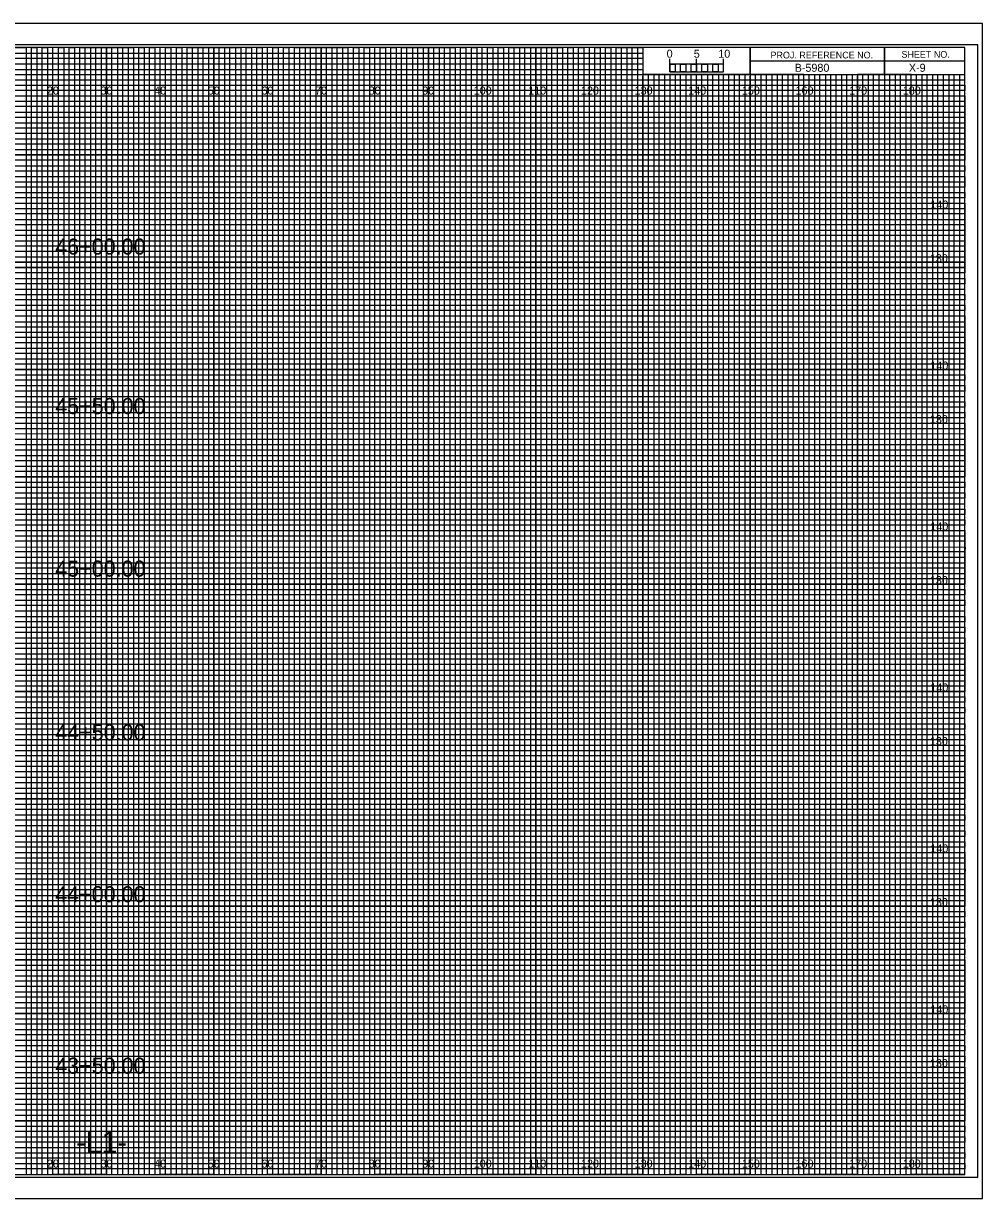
# Model space of a CAD drawing. Extents: x -13 to 323, y -5 to 3294.
# Drawn here: x 144.5 to 323.3, y 1755.5 to 1974.5 of the extents above; entities that cross this region are included whole.
import ezdxf

# ---------------------------------------------------------------- set-up
doc = ezdxf.new("R2010")
doc.units = 0
for name, color, linetype in [('Prop XS Alignment Label', 7, 'Continuous'), ('Prop XS Bar Scale Labels', 7, 'Continuous'), ('Prop XS Elevation Labels', 7, 'Continuous'), ('Prop XS Offset Labels', 7, 'Continuous'), ('Prop XS Project Number', 7, 'Continuous'), ('Prop XS Sheet Number', 7, 'Continuous'), ('Prop XS Station Labels', 7, 'Continuous'), ('Scratch_Level_0', 7, 'Continuous'), ('Sheet Cross Section CELL', 7, 'Continuous'), ('Sheet Cross Section Grid Major CELL', 7, 'Continuous'), ('Sheet Cross Section Grid Middle CELL', 7, 'Continuous'), ('Sheet Cross Section Grid Minor 1 CELL', 7, 'Continuous'), ('Sheet Cross Section Grid Minor 2 CELL', 7, 'Continuous'), ('Sheet Cross Section Scale CELL', 7, 'Continuous'), ('Sheet Cutting Line CELL', 7, 'Continuous'), ('Sheet DOT Grid CELL', 7, 'Continuous'), ('Sheet Plot Border Inside CELL', 7, 'Continuous'), ('Sheet Plot Border Outside CELL', 7, 'Continuous')]:
    doc.layers.add(name, color=color, linetype=linetype)

msp = doc.modelspace()

# ---------------------------------------------------------------- linework, layer by layer
at = {"layer": 'Scratch_Level_0'}
msp.add_lwpolyline([(310, 1800), (10, 1800), (10, 1770), (310, 1770)], close=True, dxfattribs=at)
at = {"layer": 'Sheet Cross Section CELL'}
for p, q in [((305, 1970), (305, 1965)), ((305, 1965), (305, 1970)), ((280, 1967.5), (280, 1965)), ((320, 1967.49), (280, 1967.49)), ((280, 1965), (320, 1965))]:
    msp.add_line(p, q, dxfattribs=at)
for points in [[(320, 1970), (0, 1970), (0, 1760), (320, 1760)], [(280, 1970), (260, 1970), (260, 1965.03), (280, 1965.03)], [(320, 1970), (280, 1970), (280, 1965), (320, 1965)]]:
    msp.add_lwpolyline(points, close=True, dxfattribs=at)
at = {"layer": 'Sheet Cross Section Grid Major CELL'}
for p, q in [((150, 1970), (140, 1970)), ((150, 1760), (150, 1970)), ((170, 1970), (160, 1970)), ((160, 1970), (160, 1760)), ((170, 1760), (170, 1970)), ((190, 1970), (180, 1970)), ((180, 1970), (180, 1760)), ((190, 1760), (190, 1970)), ((210, 1970), (200, 1970)), ((200, 1970), (200, 1760)), ((210, 1760), (210, 1970)), ((230, 1970), (220, 1970)), ((220, 1970), (220, 1760)), ((230, 1760), (230, 1970)), ((250, 1970), (240, 1970)), ((240, 1970), (240, 1760)), ((250, 1760), (250, 1970)), ((260, 1970), (260, 1760)), ((270, 1760), (270, 1965)), ((290, 1965), (280, 1965)), ((280, 1965), (280, 1760)), ((290, 1760), (290, 1965)), ((310, 1965), (300, 1965)), ((300, 1965), (300, 1760)), ((310, 1760), (310, 1965)), ((160, 1760), (150, 1760)), ((180, 1760), (170, 1760)), ((200, 1760), (190, 1760)), ((220, 1760), (210, 1760)), ((240, 1760), (230, 1760)), ((260, 1760), (250, 1760)), ((280, 1760), (270, 1760)), ((300, 1760), (290, 1760)), ((320, 1760), (310, 1760)), ((320, 1760), (320, 1760))]:
    msp.add_line(p, q, dxfattribs=at)
for points in [[(0, 1960), (320, 1960), (320, 1950), (0, 1950)], [(0, 1940), (320, 1940), (320, 1930), (0, 1930)], [(0, 1920), (320, 1920), (320, 1910), (0, 1910)], [(0, 1900), (320, 1900), (320, 1890), (0, 1890)], [(0, 1880), (320, 1880), (320, 1870), (0, 1870)], [(0, 1860), (320, 1860), (320, 1850), (0, 1850)], [(0, 1840), (320, 1840), (320, 1830), (0, 1830)], [(0, 1820), (320, 1820), (320, 1810), (0, 1810)], [(0, 1800), (320, 1800), (320, 1790), (0, 1790)], [(0, 1780), (320, 1780), (320, 1770), (0, 1770)]]:
    msp.add_lwpolyline(points, dxfattribs=at)
at = {"layer": 'Sheet Cross Section Grid Middle CELL'}
for points in [[(135, 1970), (145, 1970), (145, 1760), (155, 1760), (155, 1970), (165, 1970), (165, 1760), (175, 1760), (175, 1970), (185, 1970), (185, 1760), (195, 1760), (195, 1970), (205, 1970), (205, 1760), (215, 1760), (215, 1970), (225, 1970), (225, 1760), (235, 1760), (235, 1970), (245, 1970), (245, 1760), (255, 1760), (255, 1970), (259.93, 1970), (260, 1970), (260, 1965), (264.99, 1965), (264.99, 1760), (275, 1760), (275, 1965), (285, 1965), (285, 1760), (295, 1760), (295, 1965), (305, 1965), (305, 1760), (315, 1760), (315, 1965)], [(0, 1965), (275, 1965)], [(0, 1945), (320, 1945), (320, 1955), (0, 1955)], [(0, 1925), (320, 1925), (320, 1935), (0, 1935)], [(0, 1905), (320, 1905), (320, 1915), (0, 1915)], [(0, 1885), (320, 1885), (320, 1895), (0, 1895)], [(0, 1865), (320, 1865), (320, 1875), (0, 1875)], [(0, 1845), (320, 1845), (320, 1855), (0, 1855)], [(0, 1825), (320, 1825), (320, 1835), (0, 1835)], [(0, 1805), (320, 1805), (320, 1815), (0, 1815)], [(0, 1785), (320, 1785), (320, 1795), (0, 1795)], [(0, 1765), (320, 1765), (320, 1775), (0, 1775)]]:
    msp.add_lwpolyline(points, dxfattribs=at)
at = {"layer": 'Sheet Cross Section Grid Minor 1 CELL'}
for p, q in [((0, 1969), (260, 1969)), ((260, 1969), (260, 1967.98)), ((260, 1967.98), (0, 1967.98)), ((0, 1967), (260, 1967)), ((260, 1967), (260, 1965.89)), ((260, 1965.89), (0, 1965.89)), ((0, 1964), (320, 1964))]:
    msp.add_line(p, q, dxfattribs=at)
for points in [[(0, 1963), (270, 1963), (320, 1963), (320, 1962), (0, 1962)], [(0, 1961), (320, 1961), (320, 1959), (0, 1959)], [(0, 1958), (320, 1958), (320, 1957), (0, 1956.98)], [(0, 1956), (320, 1956), (320, 1954), (0, 1954)], [(0, 1953), (320, 1953), (320, 1952), (0, 1952)], [(0, 1951), (320, 1951), (320, 1949), (0, 1949)], [(0, 1948), (320, 1948), (320, 1947), (0, 1947)], [(0, 1946), (320, 1946), (320, 1944), (0, 1944)], [(0, 1943), (320, 1943), (320, 1942), (0, 1942)], [(0, 1941), (320, 1941), (320, 1939), (0, 1939)], [(0, 1938), (320, 1938), (320, 1937), (0, 1937)], [(0, 1936), (320, 1936), (320, 1933.95), (320, 1933), (320, 1932), (0, 1932)], [(0, 1934), (320, 1934), (320, 1933), (0, 1933)], [(0, 1931), (320, 1931), (320, 1929), (0, 1929.03)], [(0, 1929.03), (320, 1929), (320, 1928), (0, 1928)], [(0, 1927), (320, 1927), (320, 1926), (0, 1926)], [(0, 1924), (320, 1924), (320, 1923), (0, 1923)], [(0, 1922), (320, 1922), (320, 1921), (0, 1921)], [(-0.07, 1918.89), (320, 1918.89), (320, 1917.88), (-0.07, 1917.88)], [(0, 1917), (320, 1917), (320, 1916), (0, 1916)], [(0, 1914), (320, 1914), (320, 1913), (0, 1913)], [(0, 1912), (320, 1912), (320, 1911), (0, 1911)], [(0, 1909), (320, 1909), (320, 1908), (0, 1908)], [(0, 1907), (320, 1907), (320, 1906), (0, 1906)], [(0, 1904), (320, 1904), (320, 1903), (0, 1903)], [(0, 1902), (320, 1902), (320, 1901), (0, 1901)], [(0, 1899), (320, 1899), (319.99, 1897.98), (0, 1898)], [(0, 1897), (320, 1897), (320, 1896), (0, 1896)], [(0, 1894), (320, 1894), (320, 1893), (0, 1893)], [(0, 1892), (320, 1892), (320, 1891), (0, 1891)], [(0, 1889), (320, 1889), (320, 1888), (0, 1888)], [(0, 1887), (320, 1887), (320, 1886), (0, 1886)], [(0, 1884), (320, 1884), (320, 1883), (0, 1883)], [(0, 1882), (320, 1882), (320, 1881), (0, 1881)], [(0, 1879), (320, 1879), (320, 1878), (0, 1878)], [(0, 1876.99), (320.07, 1876.91), (320, 1876), (0, 1876)], [(0, 1874), (320, 1874), (320, 1873), (0, 1873)], [(0, 1872), (320, 1872), (320, 1871), (0, 1871)], [(0, 1869), (320, 1869), (320, 1868), (0, 1868)], [(0, 1867), (320, 1867), (320, 1866), (0, 1866)], [(0, 1864), (320, 1864), (320, 1863), (0, 1863)], [(0, 1862), (320, 1862), (320, 1861), (0, 1861)], [(0, 1859), (320, 1859), (320, 1858), (0, 1858)], [(0, 1857), (320, 1857), (320, 1856), (0, 1856)], [(0, 1854), (320, 1854), (320, 1853), (0, 1853)], [(0, 1852), (320, 1852), (320, 1851), (0, 1851)], [(0, 1849), (320, 1849), (320, 1848), (0, 1848)], [(0, 1847), (320, 1847), (320, 1846), (0, 1846)], [(0, 1844), (320, 1844), (320, 1843), (0, 1843)], [(0, 1842), (320, 1842), (320, 1841), (0, 1841)], [(0, 1839), (320, 1839), (319.99, 1837.98), (0, 1838)], [(0, 1837), (320, 1837), (320, 1836), (0, 1836)], [(0, 1834), (320, 1834), (320, 1833), (0, 1833)], [(0, 1832), (320, 1832), (320, 1831), (0, 1831)], [(0, 1829), (320, 1829), (320, 1828), (0, 1828)], [(0, 1827), (320, 1827), (320, 1826), (0, 1826)], [(0, 1824), (320, 1824), (320, 1823), (0, 1823)], [(0, 1822), (320, 1822), (320, 1821), (0, 1821)], [(0, 1819), (320, 1819), (320, 1818), (0, 1818)], [(0, 1816.99), (320.07, 1816.91), (320, 1816), (0, 1816)], [(0, 1814), (320, 1814), (320, 1813), (0, 1813)], [(0, 1812), (320, 1812), (320, 1811), (0, 1811)], [(0, 1809), (320, 1809), (320, 1808), (0, 1808)], [(0, 1807), (320, 1807), (320, 1806), (0, 1806)], [(0, 1804), (320, 1804), (320, 1803), (0, 1803)], [(0, 1802), (320, 1802), (320, 1801), (0, 1801)], [(0, 1799), (320, 1799), (320, 1798), (0, 1798)], [(0, 1797), (320, 1797), (320, 1796), (0, 1796)], [(0, 1794), (320, 1794), (320, 1793), (0, 1793)], [(0, 1792), (320, 1792), (320, 1791), (0, 1791)], [(0, 1789), (320, 1789), (320, 1788), (0, 1788)], [(0, 1787), (320, 1787), (320, 1786), (0, 1786)], [(0, 1784), (320, 1784), (320, 1783), (0, 1783)], [(0, 1782), (320, 1782), (320, 1781), (0, 1781)], [(0, 1779), (320, 1779), (320, 1778), (0, 1778)], [(0, 1777), (320, 1777), (320, 1776), (0, 1776)], [(0, 1774), (320, 1774), (320, 1773), (0, 1773)], [(0, 1772), (320, 1772), (320, 1771), (0, 1771)], [(0, 1769), (320, 1769), (320, 1768), (0, 1768)], [(0, 1767), (320, 1767), (320, 1766), (0, 1766)], [(0, 1764), (320, 1764), (320, 1763), (0, 1763)], [(0, 1762), (320, 1762), (320, 1761), (0, 1761)]]:
    msp.add_lwpolyline(points, dxfattribs=at)
at = {"layer": 'Sheet Cross Section Grid Minor 2 CELL'}
for p, q in [((267, 1965), (266.01, 1965)), ((266.01, 1965), (266.01, 1760)), ((267, 1760), (267, 1965)), ((269, 1965), (268, 1965)), ((268, 1965), (268, 1760)), ((269, 1760), (269, 1965)), ((266.01, 1760), (265, 1760)), ((268, 1760), (267, 1760))]:
    msp.add_line(p, q, dxfattribs=at)
for points in [[(145, 1760), (146, 1760), (146, 1970), (147, 1970), (147, 1760)], [(147, 1760), (148, 1760), (148, 1970), (149, 1970), (149, 1760)], [(150, 1760), (151, 1760), (151, 1970), (152, 1970), (152, 1760)], [(152, 1760), (153, 1760), (153, 1970), (154, 1970), (154, 1760)], [(155, 1760), (156, 1760), (156, 1970), (157, 1970), (157, 1760)], [(157, 1760), (158, 1760), (158, 1970), (159, 1970), (159, 1760)], [(160, 1760), (161, 1760), (161, 1970), (162, 1970), (162, 1760)], [(162, 1760), (163, 1760), (163, 1970), (164, 1970), (164, 1760)], [(165, 1760), (166, 1760), (166, 1970), (167, 1970), (167, 1760)], [(167, 1760), (168, 1760), (168, 1970), (169, 1970), (169, 1760)], [(170, 1760), (171, 1760), (171, 1970), (172, 1970), (172, 1760)], [(172, 1760), (173, 1760), (173, 1970), (174, 1970), (174, 1760)], [(175, 1760), (176, 1760), (176, 1970), (177, 1970), (177, 1760)], [(177, 1760), (178, 1760), (178, 1970), (179, 1970), (179, 1760)], [(180, 1760), (181, 1760), (181, 1970), (182, 1970), (182, 1760)], [(182, 1760), (183, 1760), (183, 1970), (184, 1970), (184, 1760)], [(185, 1760), (186, 1760), (186, 1970), (187, 1970), (187, 1760)], [(187, 1760), (188, 1760), (188, 1970), (189, 1970), (189, 1760)], [(190, 1760), (191, 1760), (191, 1970), (192, 1970), (192, 1760)], [(192, 1760), (193, 1760), (193, 1970), (194, 1970), (194, 1760)], [(195, 1760), (196, 1760), (196, 1970), (197, 1970), (197, 1760)], [(197, 1760), (198, 1760), (198, 1970), (199, 1970), (199, 1760)], [(200, 1760), (201, 1760), (201, 1970), (202, 1970), (202, 1760)], [(202, 1760), (203, 1760), (203, 1970), (204, 1970), (204, 1760)], [(205, 1760), (206, 1760), (206, 1970), (207, 1970), (207, 1760)], [(207, 1760), (208, 1760), (208, 1970), (209, 1970), (209, 1760)], [(210, 1760), (211, 1760), (211, 1970), (212, 1970), (212, 1760)], [(212, 1760), (213, 1760), (213, 1970), (214, 1970), (214, 1760)], [(215, 1760), (216, 1760), (216, 1970), (217, 1970), (217, 1760)], [(217, 1760), (218, 1760), (218, 1970), (219, 1970), (219, 1760)], [(220, 1760), (221, 1760), (221, 1970), (222, 1970), (222, 1760)], [(222, 1760), (223, 1760), (223, 1970), (224, 1970), (224, 1760)], [(225, 1760), (226, 1760), (226, 1970), (227, 1970), (227, 1760)], [(227, 1760), (228, 1760), (228, 1970), (229, 1970), (229, 1760)], [(230, 1760), (231, 1760), (231, 1970), (232, 1970), (232, 1760)], [(232, 1760), (233, 1760), (233, 1970), (234, 1970), (234, 1760)], [(235, 1760), (236, 1760), (236, 1970), (237, 1970), (237, 1760)], [(237, 1760), (238, 1760), (238, 1970), (239, 1970), (239, 1760)], [(240, 1760), (241, 1760), (241, 1970), (242, 1970), (242, 1760)], [(242, 1760), (243, 1760), (243, 1970), (244, 1970), (244, 1760)], [(245, 1760), (246, 1760), (246, 1970), (247, 1970), (247, 1760)], [(247, 1760), (248, 1760), (248, 1970), (249, 1970), (249, 1760)], [(250, 1760), (251, 1760), (251, 1970), (252, 1970), (252, 1760)], [(252, 1760), (253, 1760), (253, 1970), (254, 1970), (254, 1760)], [(255, 1760), (256, 1760), (256, 1970), (257, 1970), (257, 1760)], [(257, 1760), (258, 1760), (258, 1970), (259, 1970), (259, 1760)], [(260, 1760), (261, 1760), (261, 1965), (262.02, 1965), (262.02, 1760)], [(262, 1760), (263, 1760), (263, 1965), (263.99, 1965), (263.99, 1760)], [(270, 1760), (270.98, 1760), (270.98, 1965), (272, 1965), (272, 1760)], [(272, 1760), (273, 1760), (273, 1965), (274.05, 1965), (274.05, 1760)], [(275, 1760), (276, 1760), (276, 1965), (277, 1965), (277, 1760)], [(277, 1760), (278, 1760), (278, 1965), (279, 1965), (279, 1760)], [(280, 1760), (281, 1760), (281, 1965), (282, 1965), (282, 1760)], [(282, 1760), (283, 1760), (283, 1965), (284, 1965), (284, 1760)], [(285, 1760), (286, 1760), (286, 1965), (287, 1965), (287, 1760)], [(287, 1760), (288, 1760), (288, 1965), (289, 1965), (289, 1760)], [(290, 1760), (291, 1760), (291, 1965), (292, 1965), (292, 1760)], [(292, 1760), (293, 1760), (293, 1965), (294, 1965), (294, 1760)], [(295, 1760), (296, 1760), (296, 1965), (297, 1965), (297, 1760)], [(297, 1760), (298, 1760), (298, 1965), (299, 1965), (299, 1760)], [(300, 1760), (301, 1760), (301, 1965), (302, 1965), (302, 1760)], [(302, 1760), (303, 1760), (303, 1965), (304, 1965), (304, 1760)], [(305, 1760), (306, 1760), (306, 1965), (307, 1965), (307, 1760)], [(307, 1760), (308, 1760), (308, 1965), (309, 1965), (309, 1760)], [(310, 1760), (311, 1760), (311, 1965), (312, 1965), (312, 1760)], [(312, 1760), (313, 1760), (313, 1965), (314, 1965), (314, 1760)], [(315, 1760), (316, 1760), (316, 1965), (317, 1965), (317, 1760)], [(317, 1760), (318, 1760), (318, 1965), (319, 1965), (319, 1760)]]:
    msp.add_lwpolyline(points, dxfattribs=at)
at = {"layer": 'Sheet Cross Section Scale CELL'}
for p, q in [((265, 1965.49), (265, 1967.9)), ((265, 1966.9), (265, 1967.9)), ((270, 1965.49), (270, 1967.9)), ((275, 1965.49), (275, 1967.9)), ((275, 1966.9), (275, 1967.9))]:
    msp.add_line(p, q, dxfattribs=at)
for points in [[(275, 1966.9), (265, 1966.9), (265, 1965.49), (275, 1965.49)], [(265, 1966.9), (266, 1966.9), (266, 1965.49), (265, 1965.49)], [(267, 1966.9), (268, 1966.9), (268, 1965.49), (267, 1965.49)], [(269, 1966.9), (270, 1966.9), (270, 1965.49), (269, 1965.49)], [(271, 1966.9), (272, 1966.9), (272, 1965.49), (271, 1965.49)], [(273, 1966.9), (274, 1966.9), (274, 1965.49), (273, 1965.49)]]:
    msp.add_lwpolyline(points, close=True, dxfattribs=at)
at = {"layer": 'Sheet Cutting Line CELL'}
for p, q in [((323.3, 1974.5), (-13.4, 1974.5)), ((-13.4, 1755.5), (323.3, 1755.5))]:
    msp.add_line(p, q, dxfattribs=at)
at = {"layer": 'Sheet DOT Grid CELL'}
for p, q in [((150, 1760), (150, 1970)), ((160, 1760), (160, 1970)), ((170, 1760), (170, 1970)), ((180, 1760), (180, 1970)), ((190, 1760), (190, 1970)), ((200, 1760), (200, 1970)), ((210, 1760), (210, 1970)), ((220, 1760), (220, 1970)), ((230, 1760), (230, 1970)), ((240, 1760), (240, 1970)), ((250, 1760), (250, 1970)), ((260, 1760), (260, 1964.69)), ((270, 1760), (270, 1964.69)), ((280, 1760), (280, 1964.69)), ((290, 1760), (290, 1964.69)), ((300, 1760), (300, 1964.69)), ((310, 1760), (310, 1964.69)), ((0, 1960), (320, 1960)), ((0, 1950), (320, 1950)), ((0, 1940), (320, 1940)), ((0, 1930), (320, 1930)), ((0, 1920), (320, 1920)), ((0, 1910), (320, 1910)), ((0, 1900), (320, 1900)), ((0, 1890), (320, 1890)), ((0, 1880), (320, 1880)), ((0, 1870), (320, 1870)), ((0, 1860), (320, 1860)), ((0, 1850), (320, 1850)), ((0, 1840), (320, 1840)), ((0, 1830), (320, 1830)), ((0, 1820), (320, 1820)), ((0, 1810), (320, 1810)), ((0, 1800), (320, 1800)), ((0, 1790), (320, 1790)), ((0, 1780), (320, 1780)), ((0, 1770), (320, 1770))]:
    msp.add_line(p, q, dxfattribs=at)
at = {"layer": 'Sheet Plot Border Inside CELL'}
msp.add_lwpolyline([(-10.8, 1759.5), (322.4, 1759.5), (322.4, 1970.5), (-10.8, 1970.5)], close=True, dxfattribs=at)
at = {"layer": 'Sheet Plot Border Outside CELL'}
msp.add_lwpolyline([(-13.4, 1755.5), (323.3, 1755.5), (323.3, 1974.5), (-13.4, 1974.5)], close=True, dxfattribs=at)

# ---------------------------------------------------------------- texts
at = {"layer": 'Prop XS Alignment Label'}
msp.add_text('-L1-', height=4, dxfattribs=at).set_placement((154.28, 1764))
at = {"layer": 'Prop XS Bar Scale Labels'}
for s, p in [('5', (269.47, 1968.12)), ('10', (274.04, 1968.12))]:
    msp.add_text(s, height=1.5, dxfattribs=at).set_placement(p)
at = {"layer": 'Prop XS Elevation Labels'}
for s, p in [('140', (313.57, 1940)), ('130', (313.49, 1930)), ('140', (313.57, 1910)), ('130', (313.49, 1900)), ('140', (313.57, 1880)), ('130', (313.49, 1870)), ('140', (313.57, 1850)), ('130', (313.49, 1840)), ('140', (313.57, 1820)), ('130', (313.49, 1810)), ('140', (313.57, 1790)), ('130', (313.49, 1780))]:
    msp.add_text(s, height=1.5, dxfattribs=at).set_placement(p)
at = {"layer": 'Prop XS Offset Labels'}
for s, p in [('20', (148.86, 1961.25)), ('30', (158.86, 1961.25)), ('40', (168.86, 1961.25)), ('50', (178.86, 1961.25)), ('60', (188.86, 1961.25)), ('70', (198.86, 1961.25)), ('80', (208.86, 1961.25)), ('90', (218.86, 1961.25)), ('100', (228.44, 1961.25)), ('110', (238.62, 1961.25)), ('120', (248.44, 1961.25)), ('130', (258.44, 1961.25)), ('140', (268.44, 1961.25)), ('150', (278.44, 1961.25)), ('160', (288.44, 1961.25)), ('170', (298.44, 1961.25)), ('180', (308.44, 1961.25)), ('20', (148.86, 1761.25)), ('30', (158.86, 1761.25)), ('40', (168.86, 1761.25)), ('50', (178.86, 1761.25)), ('60', (188.86, 1761.25)), ('70', (198.86, 1761.25)), ('80', (208.86, 1761.25)), ('90', (218.86, 1761.25)), ('100', (228.44, 1761.25)), ('110', (238.62, 1761.25)), ('120', (248.44, 1761.25)), ('130', (258.44, 1761.25)), ('140', (268.44, 1761.25)), ('150', (278.44, 1761.25)), ('160', (288.44, 1761.25)), ('170', (298.44, 1761.25)), ('180', (308.44, 1761.25))]:
    msp.add_text(s, height=1.5, dxfattribs=at).set_placement(p)
at = {"layer": 'Prop XS Project Number'}
msp.add_text('B-5980', height=1.5, dxfattribs=at).set_placement((288.28, 1965.5))
at = {"layer": 'Prop XS Sheet Number'}
msp.add_text('X-9', height=1.5, dxfattribs=at).set_placement((309.57, 1965.5))
at = {"layer": 'Prop XS Station Labels'}
for s, p in [('46+00.00', (150.41, 1931.43)), ('45+50.00', (150.41, 1901.7)), ('45+00.00', (150.41, 1871.4)), ('44+50.00', (150.41, 1840.88)), ('44+00.00', (150.41, 1810.71)), ('43+50.00', (150.41, 1778.75))]:
    msp.add_text(s, height=3, dxfattribs=at).set_placement(p)
at = {"layer": 'Sheet Cross Section CELL'}
for s, p in [('PROJ. REFERENCE NO.', (283.77, 1967.99)), ('SHEET NO.', (308.19, 1968.12))]:
    msp.add_text(s, height=1.25, dxfattribs=at).set_placement(p)
at = {"layer": 'Sheet Cross Section Scale CELL'}
msp.add_text('0', height=1.5, dxfattribs=at).set_placement((264.41, 1968.12))

doc.saveas('drawing.dxf')
